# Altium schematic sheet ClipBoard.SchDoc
size A4
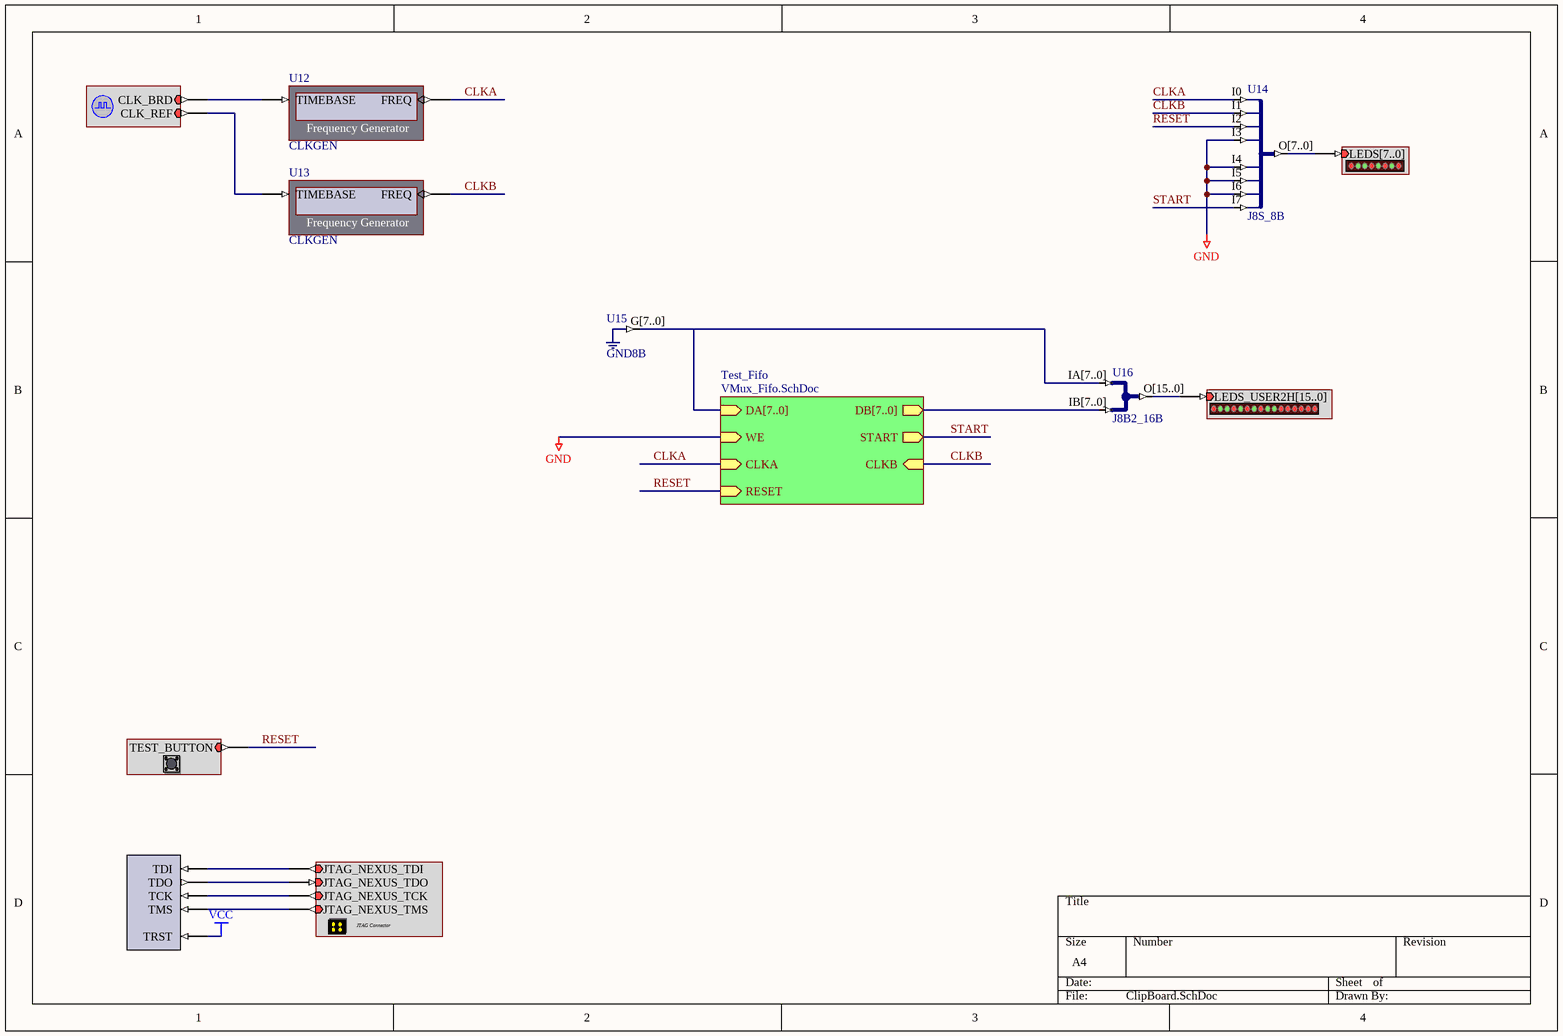
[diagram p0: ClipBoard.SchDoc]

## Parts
(Parts that share a designator on the sheet are numbered #1, #2 ... from top to bottom, then left to right.)
?#1  LEDX16USERIO2  (value not drawn)
?#2  CLOCK_SUPPLY  (value not drawn)
?#3  LED  (value not drawn)
?#4  TEST_BUTTON  (value not drawn)
?#5  NEXUS_JTAG_PORT  (value not drawn)
?#6  NEXUS_JTAG_CONNECTOR  (value not drawn)
U12  CLKGEN
U13  CLKGEN
U14  J8S_8B
U15  GND8B
U16  J8B2_16B

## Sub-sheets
Test_Fifo = VMux_Fifo.SchDoc: DA[7..0] (in), CLKA (in), WE (in), START (out), DB[7..0] (out), CLKB (in), RESET (in)

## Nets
GND: U14.I3 U14.I4 U14.I5 U14.I6 ; sheet Test_Fifo/WE
VCC: ?#5.TRST
CLKA: U12.FREQ U14.I0 ; sheet Test_Fifo/CLKA
CLKB: U13.FREQ U14.I1 ; sheet Test_Fifo/CLKB
RESET: ?#4.TEST_BUTTON U14.I2 ; sheet Test_Fifo/RESET
START: U14.I7 ; sheet Test_Fifo/START
Net?#2_CLK_BRD: ?#2.CLK_BRD U12.TIMEBASE
Net?#2_CLK_REF: ?#2.CLK_REF U13.TIMEBASE
Net?#5_TCK: ?#5.TCK ?#6.JTAG_NEXUS_TCK
Net?#5_TDI: ?#5.TDI ?#6.JTAG_NEXUS_TDI
Net?#5_TDO: ?#5.TDO ?#6.JTAG_NEXUS_TDO
Net?#5_TMS: ?#5.TMS ?#6.JTAG_NEXUS_TMS

Not connected (* = marked no-connect by the designer): ?#1 LEDS_USER2H[15..0]; ?#3 LEDS[7..0]; U14 O[7..0]; U15 G[7..0]; U16 IA[7..0] IB[7..0] O[15..0]

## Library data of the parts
?#1 = LEDX16USERIO2: 16x LED User Module; PortComponent: True
?#2 = CLOCK_SUPPLY: Global System Clock and Reference Suply; PortComponent: True
?#3 = LED: 8-Way LEDS; PortComponent: True
?#4 = TEST_BUTTON: Test Button; PortComponent: True
?#5 = NEXUS_JTAG_PORT: Nexus Processor JTAG Chain Connector; NEXUS_JTAG_CONNECTOR: True
?#6 = NEXUS_JTAG_CONNECTOR: JTAG Port; PortComponent: True
U12 U13 = CLKGEN: Frequency Generator; NEXUS_CORE: Instrument; NEXUS_JTAG_DEVICE: True; NEXUS_JTAG_ORDER: 0
U14 = J8S_8B: 8 Single pin inputs to single 8-Bit output bus; Class I: Bus Joiner; ArchiveName: GENERIC
U15 = GND8B: 8-Bit Logic '0' Bus; Class I: Power Level; ArchiveName: GENERIC
U16 = J8B2_16B: 2 x 8-Bit input bus to 1 x 16-bit output bus; Class I: Bus Joiner; ArchiveName: GENERIC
